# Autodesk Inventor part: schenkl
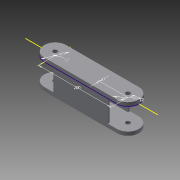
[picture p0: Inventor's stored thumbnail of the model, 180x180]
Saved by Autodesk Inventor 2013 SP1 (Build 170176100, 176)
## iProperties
Created: 2012-11
Part Number: schenkl
Material: Allgemein
Document SubType Name: Modeling
Designer: macuser
Density: 1 g/cm^3
Author: macuser
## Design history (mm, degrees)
sketch "Skizze1"
  geometry: L1 (0, -42)-(0, 42) reference; L2 (-82, 0)-(282, 0) reference; L3 (0, 30)-(200, 30); L4 (0, -30)-(200, -30); C1 r 6 at (0, 0); C2 r 6 at (200, 0); A1 r 30 centre (0, 0) between (0, 30) and (0, -30); A2 r 30 centre (200, 0) between (200, 30) and (200, -30); 1 further point
  constraints: 4 centre point, 4 end point, 4 point on circle, 2 coincident, 2 parallel, 2 point on line, 2 tangent
  dimensions: "d0" = 60 diameter of A1; "d1" = 60 diameter of A2; "d2" = 0 distance from line of L1 A1.centre; "d3" = 200 distance of A2.centre point (0, 0); "d4" = 12 diameter of C1; "d5" = 12 diameter of C2
extrude "Extrusion1" new body sketch "Skizze1" distance "d6" = 10; taper "d7" = 0 deg
sketch "Skizze2"
  geometry: L1 (0, -42)-(0, 42) reference; L2 (-82, 0)-(282, 0) reference; L3 (25, 30)-(175, 30); L4 (25, 30)-(25, 25); L5 (25, 25)-(175, 25); L6 (175, 25)-(175, 30); L7 (25, -30)-(175, -30); L8 (175, -30)-(175, -25); L9 (175, -25)-(25, -25); L10 (25, -25)-(25, -30)
  constraints: 16 end point, 4 perpendicular, 3 parallel
  dimensions: "d8" = 150 distance of L3.start L3.end; "d9" = 25 distance from line of L1 L3.start; "d12" = 5 distance of L3.start L4.end; "d13" = 30 distance between parallel lines of L2 L3; "d14" = 150 distance of L7.start L7.end; "d15" = 5 distance of L7.end L8.end; "d16" = 25 distance between parallel lines of L1 L10; "d17" = 25 distance between parallel lines of L9 L2
extrude "Extrusion2" join sketch "Skizze2" distance "d18" = 60; taper "d19" = 0 deg
sketch "Skizze3"
  geometry: L1 (-82, 0)-(282, 0) reference; L2 (0, -42)-(0, 42) reference; L3 (0, -30)-(200, -30); L4 (0, 30)-(200, 30); C1 r 6 at (200, 0); C2 r 6 at (0, 0); A1 r 30 centre (0, 0) between (0, -30) and (0, 30); A2 r 30 centre (200, 0) between (200, -30) and (200, 30); 1 further point
  constraints: 4 centre point, 4 end point, 4 point on circle, 3 coincident, 2 point on line, 2 tangent
  dimensions: "d20" = 60 diameter of A1; "d21" = 60 diameter of A2; "d22" = 200 distance of A2.centre A1.centre; "d23" = 0 distance from line of L1 A2.centre; "d25" = 12 diameter of C1; "d26" = 12 diameter of C2
extrude "Extrusion3" join sketch "Skizze3" distance "d27" = 10; taper "d28" = 0 deg
extrude "Extrusion4" cut sketch "Skizze3" distance "d29" = 10; taper "d30" = 0 deg
node "Volumenkörper1"
